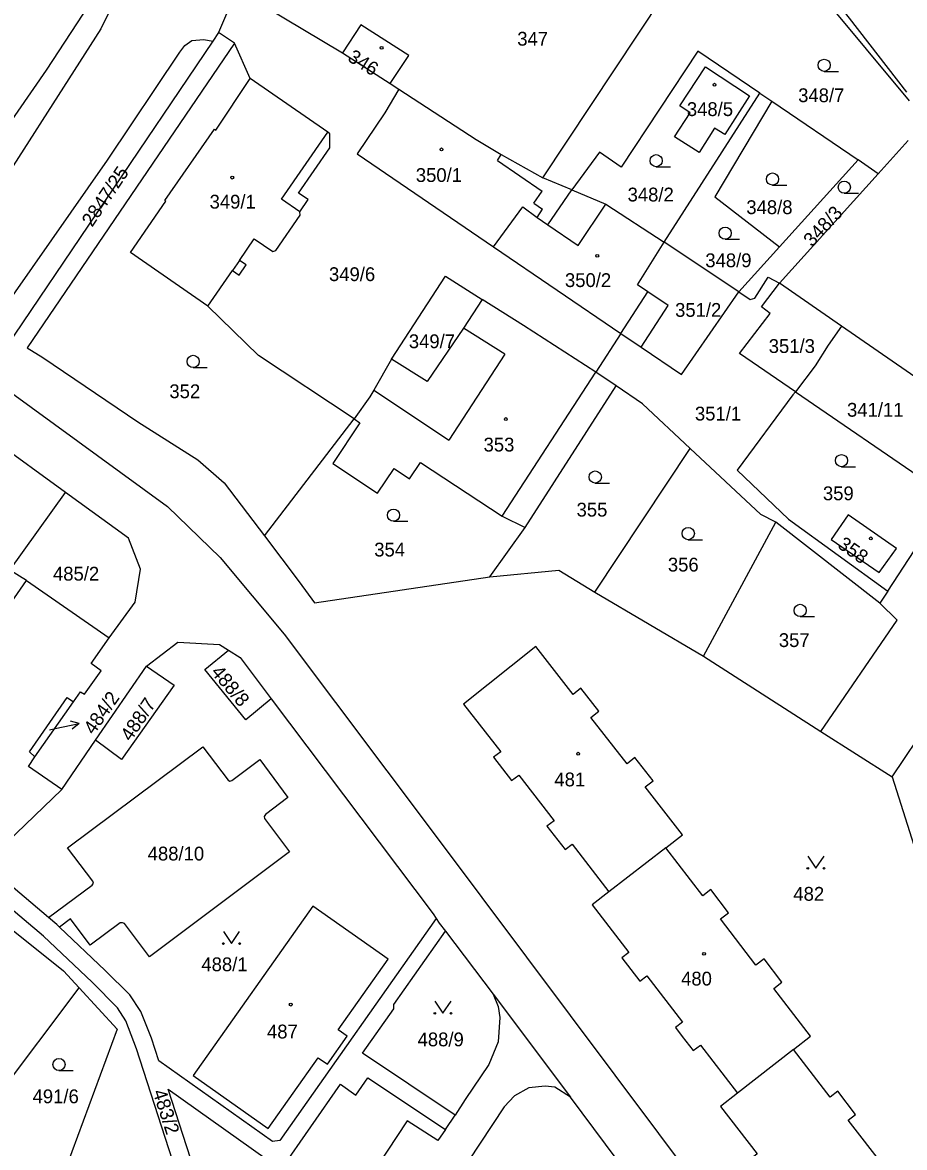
# Model space of a CAD drawing. Extents: x -558358 to -557517, y -1073786 to -1073189.
# Drawn here: x -558018.3 to -557909.7, y -1073407.2 to -1073268.6 of the extents above; entities that cross this region are included whole.
import ezdxf

# ---------------------------------------------------------------- set-up
doc = ezdxf.new("R2010")
doc.units = 0
for name, color, linetype in [('Hranice parcel', 7, 'Continuous'), ('Parcelní čísla', 7, 'Continuous'), ('Pop  PČ popisy', 7, 'Continuous'), ('Svazek obcí údolí Desné', 7, 'Continuous'), ('Vnitřní kresba', 7, 'Continuous'), ('Značky budov', 7, 'Continuous'), ('Značky kultur', 7, 'Continuous')]:
    doc.layers.add(name, color=color, linetype=linetype)

msp = doc.modelspace()

# ---------------------------------------------------------------- linework, layer by layer
at = {"layer": 'Hranice parcel'}
for p, q in [((-557909.08, -1073278.25), (-557930.32, -1073252.64)), ((-557954.2, -1073287.72), (-557935.78, -1073259.94)), ((-557991.89, -1073264.55), (-557994.13, -1073269.82)), ((-557988.45, -1073266.61), (-557978.88, -1073272.32)), ((-557994.13, -1073269.82), (-557994.86, -1073270.9)), ((-557992.18, -1073271.14), (-557994.13, -1073269.82)), ((-557994.86, -1073270.9), (-558022.09, -1073311.21)), ((-557995.96, -1073270.7), (-557994.86, -1073270.9)), ((-557990.25, -1073275.48), (-557992.18, -1073271.14)), ((-557978.88, -1073272.32), (-557973.02, -1073276.12)), ((-557973.02, -1073276.12), (-557971.93, -1073276.83)), ((-557939.28, -1073295.66), (-557927.49, -1073277.3)), ((-557927.49, -1073277.3), (-557926.01, -1073278.28)), ((-557926.01, -1073278.28), (-557915.41, -1073285.51)), ((-557912.91, -1073287.22), (-557909.23, -1073283.14)), ((-557915.41, -1073285.51), (-557925.06, -1073296.21)), ((-557912.91, -1073287.22), (-557915.41, -1073285.51)), ((-557950.63, -1073289.21), (-557954.2, -1073287.72)), ((-557925.08, -1073300.71), (-557912.91, -1073287.22)), ((-557960.27, -1073296.22), (-557944.6, -1073306.89)), ((-557930.1, -1073301.79), (-557939.28, -1073295.66)), ((-557925.06, -1073296.21), (-557930.1, -1073301.79)), ((-557927.31, -1073303.62), (-557925.08, -1073300.71)), ((-557917.44, -1073306), (-557925.08, -1073300.71)), ((-557944.6, -1073306.89), (-557947.68, -1073311.68)), ((-557944.6, -1073306.89), (-557942.12, -1073308.58)), ((-557923.1, -1073314.09), (-557930, -1073309.35)), ((-557945.18, -1073313.34), (-557947.68, -1073311.68)), ((-557956.39, -1073330.78), (-557945.18, -1073313.34)), ((-557923.1, -1073314.09), (-557906.54, -1073325.46)), ((-557988.49, -1073331.84), (-557977.43, -1073317.43)), ((-557947.81, -1073338.78), (-557936.06, -1073321.05)), ((-557911.75, -1073338.65), (-557904.1, -1073326.9)), ((-557960.73, -1073336.87), (-557956.39, -1073330.78)), ((-557934.44, -1073346.66), (-557925.54, -1073330.14)), ((-557912.73, -1073340.1), (-557925.54, -1073330.14)), ((-557911.2, -1073361.51), (-557892.99, -1073334.25)), ((-558017.77, -1073337.32), (-558007.59, -1073344.4)), ((-557947.81, -1073338.78), (-557934.44, -1073346.66)), ((-557911.75, -1073338.65), (-557912.73, -1073340.1)), ((-558009.3, -1073357), (-558003.01, -1073347.89)), ((-558003.01, -1073347.89), (-557999.59, -1073350.23)), ((-557934.44, -1073346.66), (-557919.99, -1073355.94)), ((-557999.59, -1073350.23), (-558006.08, -1073359.37)), ((-558016.74, -1073359.04), (-558011.99, -1073352.26)), ((-557919.99, -1073355.94), (-557911.2, -1073361.51)), ((-558013.44, -1073363.06), (-558009.3, -1073357)), ((-558006.08, -1073359.37), (-558009.3, -1073357)), ((-557911.2, -1073361.51), (-557908.52, -1073369.92)), ((-557939.06, -1073370.25), (-557946.07, -1073375.66)), ((-557967.34, -1073378.97), (-557986.61, -1073406.29)), ((-557972.56, -1073389.56), (-557966.21, -1073380.53)), ((-557966.21, -1073380.53), (-557960.31, -1073388.29)), ((-558024.42, -1073404.91), (-558011.29, -1073387.48)), ((-557960.31, -1073388.29), (-557950.81, -1073400.97)), ((-557960.31, -1073388.29), (-557959.73, -1073389.78)), ((-557923.37, -1073395.09), (-557930.26, -1073400.48)), ((-557950.81, -1073400.97), (-557952.73, -1073399.73)), ((-557966.19, -1073404.96), (-557964.99, -1073403.16))]:
    msp.add_line(p, q, dxfattribs=at)
for points in [[(-557998.11, -1073217.81), (-557996.7, -1073222.28), (-557998.38, -1073242.39), (-558002.78, -1073257.43), (-558008.62, -1073269.37), (-558024.06, -1073293.44), (-558032.02, -1073303.96), (-558033.31, -1073305.78)], [(-557930.24, -1073250.53), (-557916.49, -1073268.06), (-557909.46, -1073277.19)], [(-557973.02, -1073276.12), (-557970.72, -1073272.68), (-557976.62, -1073268.9), (-557978.88, -1073272.32)], [(-558021.55, -1073305.19), (-558007.79, -1073285.56), (-557998.91, -1073272.25), (-557998.29, -1073271.45), (-557997.41, -1073270.82), (-557995.96, -1073270.7)], [(-557992.18, -1073271.14), (-558017.7, -1073308.66), (-558015.75, -1073309.85), (-558004.08, -1073317.8), (-557996.67, -1073322.48), (-557993.43, -1073325.31), (-557988.49, -1073331.84)], [(-557927.49, -1073277.3), (-557935.12, -1073272.11), (-557944.58, -1073286.41), (-557947.22, -1073284.58), (-557950.63, -1073289.21)], [(-557937.99, -1073282.67), (-557936.08, -1073279.73), (-557937.34, -1073278.85), (-557934.2, -1073274.07), (-557928.77, -1073277.64), (-557931.8, -1073282.4), (-557933.09, -1073281.6), (-557934.98, -1073284.6), (-557937.99, -1073282.67)], [(-557995.47, -1073303.55), (-558004.99, -1073296.92), (-558000.61, -1073290.62), (-558000.75, -1073290.52), (-557994.62, -1073281.73), (-557994.47, -1073281.84), (-557990.25, -1073275.48)], [(-557995.47, -1073303.55), (-557992.42, -1073299.14), (-557991.6, -1073299.71), (-557990.74, -1073298.46), (-557991.57, -1073297.9), (-557989.74, -1073295.26), (-557987.45, -1073296.82), (-557987.09, -1073296.7), (-557984.08, -1073292.32), (-557984.13, -1073291.92), (-557983.12, -1073290.42), (-557984.28, -1073289.64), (-557980.42, -1073284.02), (-557980.45, -1073282.32), (-557980.68, -1073282.11), (-557990.25, -1073275.48)], [(-557971.93, -1073276.83), (-557973.65, -1073279.73), (-557977.09, -1073284.77), (-557960.27, -1073296.22)], [(-557971.93, -1073276.83), (-557962.4, -1073283.03), (-557959.33, -1073284.84), (-557954.2, -1073287.72)], [(-557926.01, -1073278.28), (-557933.02, -1073290.08), (-557925.06, -1073296.21)], [(-557960.27, -1073296.22), (-557956.66, -1073291.3), (-557954.92, -1073292.62), (-557953.6, -1073293.52), (-557950.63, -1073289.21)], [(-557950.63, -1073289.21), (-557946.45, -1073290.96), (-557939.28, -1073295.66)], [(-557942.12, -1073308.58), (-557938.8, -1073303.44), (-557941.3, -1073301.76), (-557942.56, -1073300.91), (-557939.28, -1073295.66)], [(-557972.83, -1073310.08), (-557966.21, -1073299.85), (-557961.67, -1073302.72)], [(-557930.1, -1073301.79), (-557928.7, -1073302.72), (-557928.1, -1073302.55), (-557926.47, -1073299.96), (-557925.08, -1073300.71)], [(-557942.12, -1073308.58), (-557937.16, -1073311.96), (-557930.1, -1073301.79)], [(-557977.43, -1073317.43), (-557989.2, -1073309.62), (-557995.47, -1073303.55)], [(-557961.67, -1073302.72), (-557963.96, -1073306.23), (-557968.46, -1073312.83), (-557972.83, -1073310.08)], [(-557947.68, -1073311.68), (-557956.58, -1073305.91), (-557961.67, -1073302.72)], [(-557930, -1073309.35), (-557926.23, -1073304.45), (-557927.31, -1073303.62)], [(-557917.44, -1073306), (-557919.08, -1073308.35), (-557920.7, -1073310.88), (-557923.1, -1073314.09)], [(-557906.54, -1073325.46), (-557900.99, -1073317.38), (-557917.44, -1073306)], [(-557972.83, -1073310.08), (-557975.02, -1073313.87), (-557975.51, -1073314.71), (-557977.43, -1073317.43)], [(-558022.09, -1073311.21), (-558020.08, -1073313.87), (-558000.41, -1073328.2), (-557993.92, -1073334.5), (-557986.04, -1073343.93), (-557967.1, -1073369.2), (-557918.24, -1073434.51), (-557914.64, -1073436.24), (-557909.55, -1073436.22), (-557905.05, -1073434.1), (-557902.57, -1073430.65), (-557891.22, -1073414.37), (-557877.97, -1073395.43)], [(-557936.06, -1073321.05), (-557941.93, -1073315.57), (-557945.18, -1073313.34)], [(-557923.1, -1073314.09), (-557923.42, -1073314.47), (-557930.3, -1073323.72), (-557923.97, -1073329.78), (-557911.75, -1073338.65)], [(-558012.98, -1073326.49), (-558021.93, -1073320.01), (-558025.13, -1073318.78), (-558028.41, -1073318.97)], [(-557977.43, -1073317.43), (-557976.74, -1073317.89), (-557980.07, -1073322.91)], [(-557925.54, -1073330.14), (-557927.37, -1073329.18), (-557936.06, -1073321.05)], [(-557980.07, -1073322.91), (-557974.55, -1073326.57), (-557972.53, -1073323.54), (-557970.61, -1073324.82)], [(-557970.61, -1073324.82), (-557969.28, -1073322.81), (-557959.2, -1073329.4), (-557956.39, -1073330.78)], [(-558017.77, -1073337.32), (-558019.82, -1073336.05), (-558012.98, -1073326.49)], [(-558007.59, -1073344.4), (-558004.4, -1073339.98), (-558003.75, -1073335.95), (-558005.22, -1073332.12), (-558012.98, -1073326.49)], [(-557916.62, -1073329.24), (-557918.71, -1073332.26), (-557912.81, -1073336.33), (-557910.69, -1073333.4), (-557916.62, -1073329.24)], [(-557988.49, -1073331.84), (-557984.2, -1073337.5), (-557982.34, -1073340.07), (-557960.73, -1073336.87)], [(-557960.73, -1073336.87), (-557952.24, -1073336.05), (-557947.81, -1073338.78)], [(-558034.47, -1073361.24), (-558036.19, -1073360.05), (-558033.38, -1073356.04), (-558031.73, -1073357.2), (-558024.67, -1073347.17), (-558026.34, -1073346.01), (-558023.11, -1073341.4), (-558021.44, -1073342.56), (-558017.77, -1073337.32)], [(-557919.99, -1073355.94), (-557910.58, -1073342.2), (-557912.73, -1073340.1)], [(-558011.99, -1073352.26), (-558011.14, -1073351.05), (-558010.65, -1073351.33), (-558008.6, -1073348.45), (-558009.82, -1073347.53), (-558007.59, -1073344.4)], [(-558003.01, -1073347.89), (-557999.15, -1073344.94), (-557994.02, -1073345.2), (-557992.92, -1073345.89)], [(-557987.64, -1073351.9), (-557990.77, -1073354.47), (-557995.82, -1073348.28), (-557992.92, -1073345.89)], [(-557992.92, -1073345.89), (-557991.47, -1073346.8), (-557987.64, -1073351.9)], [(-557939.06, -1073370.25), (-557937.03, -1073368.65), (-557941.61, -1073362.76), (-557940.64, -1073362.01), (-557942.87, -1073359.14), (-557943.85, -1073359.89), (-557948.29, -1073354.18), (-557947.32, -1073353.42), (-557949.52, -1073350.59), (-557950.49, -1073351.35), (-557955.09, -1073345.44), (-557963.96, -1073352.54), (-557959.4, -1073358.42), (-557960.27, -1073359.1), (-557958.05, -1073361.97), (-557957.18, -1073361.3), (-557952.83, -1073366.91), (-557953.7, -1073367.59), (-557951.48, -1073370.46), (-557950.61, -1073369.79), (-557946.07, -1073375.66)], [(-558016.74, -1073359.04), (-558017.42, -1073358.44), (-558012.76, -1073351.73), (-558011.99, -1073352.26)], [(-557987.64, -1073351.9), (-557967.72, -1073378.38), (-557967.34, -1073378.97)], [(-558015.07, -1073378.83), (-558021.62, -1073373.3), (-558035.88, -1073363.58), (-558050.18, -1073353.97), (-558051.46, -1073355.75)], [(-557997.16, -1073446.28), (-557996.18, -1073446.14), (-557992.37, -1073440.37), (-557993.13, -1073429.99), (-557993.58, -1073428.02), (-558004.25, -1073395), (-558005.55, -1073391.58), (-558006.57, -1073389.94), (-558009.69, -1073386.81), (-558015.69, -1073381.13), (-558022.86, -1073375.1), (-558038.38, -1073364.54), (-558051.46, -1073355.75)], [(-558015.07, -1073378.83), (-558009.7, -1073374.87), (-558009.55, -1073374.62), (-558009.63, -1073374.36), (-558012.72, -1073370.26), (-557996.07, -1073357.8), (-557992.97, -1073361.92), (-557992.74, -1073362.04), (-557992.48, -1073361.98), (-557989.05, -1073359.38), (-557985.61, -1073364.04), (-557988.36, -1073366.15), (-557988.52, -1073366.38), (-557988.48, -1073366.66), (-557985.4, -1073370.76), (-558002.63, -1073383.68), (-558005.71, -1073379.56), (-558005.98, -1073379.48), (-558006.26, -1073379.51), (-558009.96, -1073382.24), (-558012.37, -1073378.99), (-558013.71, -1073380.01)], [(-558013.44, -1073363.06), (-558017.55, -1073360.24), (-558016.74, -1073359.04)], [(-558034.47, -1073361.24), (-558024.32, -1073368.43), (-558023.47, -1073367.24), (-558020.17, -1073369.56), (-558013.44, -1073363.06)], [(-557923.37, -1073395.09), (-557921.26, -1073393.45), (-557925.78, -1073387.56), (-557924.79, -1073386.8), (-557926.98, -1073383.94), (-557927.98, -1073384.7), (-557932.34, -1073379.01), (-557931.35, -1073378.25), (-557933.54, -1073375.39), (-557934.53, -1073376.15), (-557939.06, -1073370.25)], [(-557946.07, -1073375.66), (-557948.14, -1073377.29), (-557943.62, -1073383.15), (-557944.49, -1073383.82), (-557942.29, -1073386.67), (-557941.42, -1073386), (-557937, -1073391.73), (-557937.87, -1073392.4), (-557937.04, -1073393.49), (-557935.69, -1073395.23), (-557934.82, -1073394.56), (-557930.26, -1073400.48)], [(-557973.25, -1073383.95), (-557982.53, -1073377.43), (-557997.25, -1073398.28), (-557988.03, -1073404.82), (-557981.86, -1073396.11), (-557980.74, -1073396.9), (-557978.29, -1073393.44), (-557979.41, -1073392.65), (-557973.25, -1073383.95)], [(-558020.67, -1073379.44), (-558013.21, -1073385.39), (-558011.29, -1073387.48)], [(-558013.71, -1073380.01), (-558014.05, -1073379.69), (-558015.07, -1073378.83)], [(-557967.34, -1073378.97), (-557966.98, -1073379.52), (-557966.21, -1073380.53)], [(-557986.61, -1073406.29), (-557987.5, -1073406.44), (-558001.47, -1073396.48), (-558002.38, -1073393.7), (-558003.7, -1073390.42), (-558005.05, -1073388.34), (-558008.08, -1073385.35), (-558013.71, -1073380.01)], [(-558011.29, -1073387.48), (-558006.6, -1073392.58), (-558013.61, -1073411.49)], [(-557964.99, -1073403.16), (-557976.4, -1073395.54), (-557972.54, -1073390.07), (-557972.56, -1073389.56)], [(-557959.73, -1073389.78), (-557959.52, -1073391.14), (-557959.72, -1073394.15), (-557960.86, -1073396.95), (-557963.76, -1073401.26), (-557964.99, -1073403.16)], [(-557930.26, -1073400.48), (-557932.35, -1073402.1), (-557927.81, -1073407.96), (-557928.68, -1073408.63), (-557926.46, -1073411.51), (-557925.59, -1073410.83), (-557921.19, -1073416.52), (-557922.06, -1073417.2), (-557919.87, -1073420.02), (-557919, -1073419.35), (-557914.46, -1073425.22), (-557905.47, -1073418.2), (-557910.01, -1073412.34), (-557909.08, -1073411.62), (-557911.27, -1073408.79), (-557912.2, -1073409.51), (-557916.62, -1073403.8), (-557915.7, -1073403.08), (-557917.89, -1073400.24), (-557918.82, -1073400.96), (-557923.37, -1073395.09)], [(-557990.11, -1073441.11), (-557990.95, -1073429.72), (-557991.6, -1073426.99), (-558000.34, -1073399.97), (-557986.42, -1073409.86), (-557979.13, -1073399.38), (-557977.23, -1073400.7), (-557975.75, -1073398.59), (-557966.19, -1073404.96)], [(-557952.73, -1073399.73), (-557953.94, -1073399.59), (-557955.93, -1073399.82), (-557957.72, -1073400.8), (-557958.97, -1073402.15), (-557964.89, -1073411.09), (-557965.23, -1073412.1), (-557965.04, -1073413.14)], [(-557943.74, -1073483.99), (-557922.57, -1073454.37), (-557920.54, -1073448.62), (-557920.67, -1073443.5), (-557923.32, -1073437.76), (-557933.57, -1073424.07), (-557935, -1073422.19), (-557950.81, -1073400.97)], [(-557966.19, -1073404.96), (-557967.15, -1073406.3), (-557970.9, -1073403.86), (-557989.34, -1073431.82), (-557985.62, -1073434.28), (-557990.11, -1073441.11)]]:
    msp.add_lwpolyline(points, dxfattribs=at)
at = {"layer": 'Pop  PČ popisy'}
for p, q in [((-558011.3, -1073354.94), (-558012.38, -1073354.65)), ((-558014.95, -1073355.7), (-558014.23, -1073355.56)), ((-558014.23, -1073355.56), (-558011.3, -1073354.94)), ((-558011.3, -1073354.94), (-558012.17, -1073355.63))]:
    msp.add_line(p, q, dxfattribs=at)
at = {"layer": 'Svazek obcí údolí Desné'}
msp.add_lwpolyline([(-558066.74, -1073350.64), (-558065.9, -1073348.86), (-558061.08, -1073328.44), (-558060.65, -1073327.54), (-558046.7, -1073313.29), (-558030.4, -1073296.27), (-558015.33, -1073274.48), (-558010.02, -1073266.4), (-558006.82, -1073259.79), (-558003.58, -1073251.39), (-558001.93, -1073245.63), (-558000.3, -1073233.47), (-558000.14, -1073230.76), (-558000.21, -1073228.76), (-558000.67, -1073225.31), (-558001.93, -1073222.03), (-558003.18, -1073219.55), (-558003.41, -1073218.32), (-558003.28, -1073217.31), (-558002.8, -1073216.38), (-558000.9, -1073214.81), (-557999.34, -1073213.91), (-558005.3, -1073194.99), (-558007.24, -1073189.96)], dxfattribs=at)
at = {"layer": 'Vnitřní kresba'}
for p, q in [((-557986.39, -1073290.37), (-557980.68, -1073282.11)), ((-557959.81, -1073285.59), (-557959.33, -1073284.84)), ((-557959.81, -1073285.59), (-557954.3, -1073289.39)), ((-557955.3, -1073290.85), (-557954.3, -1073289.39)), ((-557984.13, -1073291.92), (-557986.39, -1073290.37)), ((-557955.3, -1073290.85), (-557954.25, -1073291.61)), ((-557949.87, -1073296.05), (-557946.45, -1073290.96)), ((-557954.92, -1073292.62), (-557954.25, -1073291.61)), ((-557953.6, -1073293.52), (-557949.87, -1073296.05)), ((-557991.57, -1073297.9), (-557992.42, -1073299.14)), ((-557944.6, -1073306.89), (-557941.3, -1073301.76)), ((-557958.88, -1073309.45), (-557963.96, -1073306.23)), ((-557958.88, -1073309.45), (-557965.78, -1073320.06)), ((-557959.2, -1073329.4), (-557947.68, -1073311.68))]:
    msp.add_line(p, q, dxfattribs=at)
msp.add_lwpolyline([(-557975.02, -1073313.87), (-557968.52, -1073318.2), (-557965.78, -1073320.06)], dxfattribs=at)
at = {"layer": 'Značky budov'}
for centre in [(-557974.06, -1073271.72), (-557933.08, -1073276.26), (-557966.69, -1073284.23), (-557992.44, -1073287.7), (-557947.51, -1073297.34), (-557958.76, -1073317.44), (-557913.84, -1073332.14), (-557949.87, -1073358.66), (-557934.36, -1073383.3), (-557985.25, -1073389.56)]:
    msp.add_circle(centre, 0.175, dxfattribs=at)
at = {"layer": 'Značky kultur'}
for p, q in [((-557919.58, -1073274.62), (-557917.83, -1073274.62)), ((-557940.26, -1073286.37), (-557938.51, -1073286.37)), ((-557925.93, -1073288.63), (-557924.18, -1073288.63)), ((-557917.1, -1073289.64), (-557915.35, -1073289.64)), ((-557931.76, -1073295.29), (-557930.01, -1073295.29)), ((-557997.27, -1073311.09), (-557995.52, -1073311.09)), ((-557917.45, -1073323.31), (-557915.7, -1073323.31)), ((-557947.76, -1073325.33), (-557946.01, -1073325.33)), ((-557972.6, -1073330.02), (-557970.85, -1073330.02)), ((-557936.31, -1073332.3), (-557934.56, -1073332.3)), ((-557922.53, -1073341.76), (-557920.78, -1073341.76)), ((-558013.78, -1073397.68), (-558012.03, -1073397.68))]:
    msp.add_line(p, q, dxfattribs=at)
for points in [[(-557921.59, -1073371.27), (-557920.59, -1073372.77), (-557919.59, -1073371.27)], [(-557993.54, -1073380.54), (-557992.54, -1073382.04), (-557991.54, -1073380.54)], [(-557967.51, -1073389.13), (-557966.51, -1073390.63), (-557965.51, -1073389.13)]]:
    msp.add_lwpolyline(points, dxfattribs=at)
for centre, radius in [((-557919.58, -1073273.87), 0.75), ((-557940.26, -1073285.62), 0.75), ((-557925.93, -1073287.88), 0.75), ((-557917.1, -1073288.89), 0.75), ((-557931.76, -1073294.54), 0.75), ((-557997.27, -1073310.34), 0.75), ((-557917.45, -1073322.56), 0.75), ((-557947.76, -1073324.58), 0.75), ((-557972.6, -1073329.27), 0.75), ((-557936.31, -1073331.55), 0.75), ((-557922.53, -1073341.01), 0.75), ((-557921.59, -1073372.77), 0.1), ((-557919.59, -1073372.77), 0.1), ((-557993.54, -1073382.04), 0.1), ((-557991.54, -1073382.04), 0.1), ((-557967.51, -1073390.63), 0.1), ((-557965.51, -1073390.63), 0.1), ((-558013.78, -1073396.93), 0.75)]:
    msp.add_circle(centre, radius, dxfattribs=at)

# ---------------------------------------------------------------- texts
at = {"layer": 'Parcelní čísla'}
for s, p in [('347', (-557957.36, -1073271.45)), ('348/7', (-557922.78, -1073278.41)), ('348/5', (-557936.48, -1073280.12)), ('350/1', (-557969.85, -1073288.24)), ('348/2', (-557943.78, -1073290.64)), ('349/1', (-557995.24, -1073291.52)), ('348/8', (-557929.16, -1073292.2)), ('348/9', (-557934.21, -1073298.74)), ('349/6', (-557980.54, -1073300.45)), ('350/2', (-557951.49, -1073301.18)), ('351/2', (-557937.93, -1073304.85)), ('349/7', (-557970.71, -1073308.71)), ('351/3', (-557926.4, -1073309.3)), ('352', (-558000.19, -1073314.87)), ('351/1', (-557935.49, -1073317.62)), ('341/11', (-557916.76, -1073317.15)), ('353', (-557961.51, -1073321.44)), ('359', (-557919.73, -1073327.44)), ('355', (-557950.06, -1073329.45)), ('354', (-557974.97, -1073334.37)), ('356', (-557938.82, -1073336.22)), ('485/2', (-558014.52, -1073337.34)), ('357', (-557925.16, -1073345.52)), ('481', (-557952.79, -1073362.68)), ('488/10', (-558002.86, -1073371.81)), ('482', (-557923.37, -1073376.77)), ('488/1', (-557996.25, -1073385.45)), ('480', (-557937.19, -1073387.21)), ('487', (-557988.17, -1073393.73)), ('488/9', (-557969.63, -1073394.7)), ('491/6', (-558017.03, -1073401.71))]:
    msp.add_text(s, height=1.7, dxfattribs=at).set_placement(p)
for s, rotation, p in [('346', 328, (-557978.36, -1073273.25)), ('2847/25', 56, (-558009.7, -1073293.88)), ('348/3', 47, (-557921.06, -1073296.33)), ('358', 325, (-557918.04, -1073333.2)), ('488/8', 310, (-557995.15, -1073348.66)), ('484/2', 55, (-558009.5, -1073356.42)), ('488/7', 56, (-558004.94, -1073357.25)), ('483/2', 288, (-558002.27, -1073400.31))]:
    msp.add_text(s, height=1.7, rotation=rotation, dxfattribs=at).set_placement(p)

doc.saveas('drawing.dxf')
